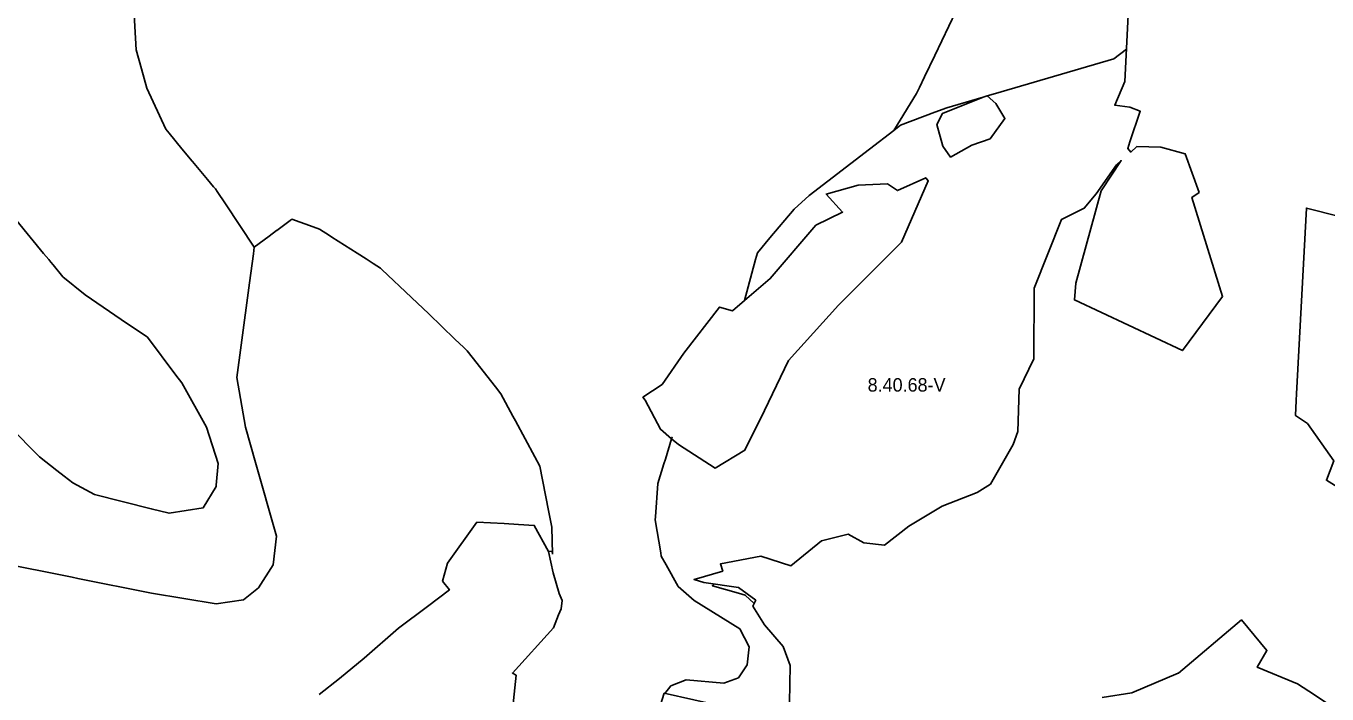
# Model space of a CAD drawing. Extents: x -547623 to -533936, y -1096714 to -1086523.
# Drawn here: x -544707 to -543738, y -1093623 to -1093125 of the extents above; entities that cross this region are included whole.
import ezdxf

# ---------------------------------------------------------------- set-up
doc = ezdxf.new("R2010")
doc.units = 0
doc.layers.add('Vrstva 27', color=7, linetype='Continuous')
doc.layers.add('Vrstva 28', color=7, linetype='Continuous')

msp = doc.modelspace()

# ---------------------------------------------------------------- linework, layer by layer
at = {"layer": 'Vrstva 28'}
for p, q in [((-543998, -1093079), (-544030.47, -1093147.12)), ((-544030.47, -1093147.12), (-543998, -1093079)), ((-544627.2, -1093102.22), (-544625.47, -1093134.21)), ((-544625.47, -1093134.21), (-544627.2, -1093102.22)), ((-544625.47, -1093134.21), (-544625, -1093143)), ((-544625, -1093143), (-544625.47, -1093134.21)), ((-544625, -1093143), (-544621.06, -1093157.03)), ((-544621.06, -1093157.03), (-544625, -1093143)), ((-543897, -1093149.5), (-543887.73, -1093142.39)), ((-543887.73, -1093142.39), (-543897, -1093149.5)), ((-544030.47, -1093147.12), (-544038.02, -1093162.95)), ((-544038.02, -1093162.95), (-544030.47, -1093147.12)), ((-543980.98, -1093174.2), (-543897, -1093149.5)), ((-543897, -1093149.5), (-543980.98, -1093174.2)), ((-544621.06, -1093157.03), (-544617, -1093171.5)), ((-544617, -1093171.5), (-544621.06, -1093157.03)), ((-544038.02, -1093162.95), (-544041.78, -1093170.85)), ((-544041.78, -1093170.85), (-544038.02, -1093162.95)), ((-544617, -1093171.5), (-544603, -1093202)), ((-544603, -1093202), (-544617, -1093171.5)), ((-544041.78, -1093170.85), (-544044, -1093175.5)), ((-544044, -1093175.5), (-544041.78, -1093170.85)), ((-543990.5, -1093177), (-543980.98, -1093174.2)), ((-543980.98, -1093174.2), (-543990.5, -1093177)), ((-544044, -1093175.5), (-544061, -1093203)), ((-544061, -1093203), (-544044, -1093175.5)), ((-544021.5, -1093186), (-543994.35, -1093178.12)), ((-543994.35, -1093178.12), (-544021.5, -1093186)), ((-543991.47, -1093177.28), (-543994.35, -1093178.12)), ((-543994.35, -1093178.12), (-543991.47, -1093177.28)), ((-543990.5, -1093177), (-543991.47, -1093177.28)), ((-543991.47, -1093177.28), (-543990.5, -1093177)), ((-544056, -1093199), (-544030.47, -1093189.38)), ((-544030.47, -1093189.38), (-544056, -1093199)), ((-544030.47, -1093189.38), (-544021.5, -1093186)), ((-544021.5, -1093186), (-544030.47, -1093189.38)), ((-544603, -1093202), (-544600.45, -1093205.07)), ((-544600.45, -1093205.07), (-544603, -1093202)), ((-544061, -1093203), (-544079.02, -1093216.88)), ((-544079.02, -1093216.88), (-544061, -1093203)), ((-544061, -1093203), (-544056, -1093199)), ((-544056, -1093199), (-544061, -1093203)), ((-544600.45, -1093205.07), (-544590.92, -1093216.53)), ((-544590.92, -1093216.53), (-544600.45, -1093205.07)), ((-544590.92, -1093216.53), (-544583.17, -1093225.85)), ((-544583.17, -1093225.85), (-544590.92, -1093216.53)), ((-544079.02, -1093216.88), (-544124, -1093251.5)), ((-544124, -1093251.5), (-544079.02, -1093216.88)), ((-544583.17, -1093225.85), (-544583.06, -1093225.98)), ((-544583.06, -1093225.98), (-544583.17, -1093225.85)), ((-544583.06, -1093225.98), (-544571.91, -1093239.39)), ((-544571.91, -1093239.39), (-544583.06, -1093225.98)), ((-544571.91, -1093239.39), (-544567.33, -1093244.9)), ((-544567.33, -1093244.9), (-544571.91, -1093239.39)), ((-544567.33, -1093244.9), (-544566, -1093246.5)), ((-544566, -1093246.5), (-544567.33, -1093244.9)), ((-544566, -1093246.5), (-544564.7, -1093248.45)), ((-544564.7, -1093248.45), (-544566, -1093246.5)), ((-544564.7, -1093248.45), (-544558.56, -1093257.66)), ((-544558.56, -1093257.66), (-544564.7, -1093248.45)), ((-544124, -1093251.5), (-544135, -1093261.5)), ((-544135, -1093261.5), (-544124, -1093251.5)), ((-544723.86, -1093258.07), (-544693.91, -1093294.48)), ((-544693.91, -1093294.48), (-544723.86, -1093258.07)), ((-544558.56, -1093257.66), (-544537, -1093290)), ((-544537, -1093290), (-544558.56, -1093257.66)), ((-544510.28, -1093269.96), (-544519.25, -1093276.69)), ((-544519.25, -1093276.69), (-544510.28, -1093269.96)), ((-544509, -1093269), (-544510.28, -1093269.96)), ((-544510.28, -1093269.96), (-544509, -1093269)), ((-544493.29, -1093274.75), (-544509, -1093269)), ((-544509, -1093269), (-544493.29, -1093274.75)), ((-544135, -1093261.5), (-544153.16, -1093282.97)), ((-544153.16, -1093282.97), (-544135, -1093261.5)), ((-544520.38, -1093277.54), (-544526.02, -1093281.76)), ((-544526.02, -1093281.76), (-544520.38, -1093277.54)), ((-544520.33, -1093277.5), (-544520.38, -1093277.54)), ((-544520.38, -1093277.54), (-544520.33, -1093277.5)), ((-544519.25, -1093276.69), (-544520.33, -1093277.5)), ((-544520.33, -1093277.5), (-544519.25, -1093276.69)), ((-544488.5, -1093276.5), (-544493.29, -1093274.75)), ((-544493.29, -1093274.75), (-544488.5, -1093276.5)), ((-544481.1, -1093281.22), (-544488.5, -1093276.5)), ((-544488.5, -1093276.5), (-544481.1, -1093281.22)), ((-544537, -1093290), (-544537.64, -1093294.82)), ((-544537.64, -1093294.82), (-544537, -1093290)), ((-544526.02, -1093281.76), (-544537, -1093290)), ((-544537, -1093290), (-544526.02, -1093281.76)), ((-544479.25, -1093282.39), (-544481.1, -1093281.22)), ((-544481.1, -1093281.22), (-544479.25, -1093282.39)), ((-544460.56, -1093294.31), (-544479.25, -1093282.39)), ((-544479.25, -1093282.39), (-544460.56, -1093294.31)), ((-544153.16, -1093282.97), (-544162.5, -1093294)), ((-544162.5, -1093294), (-544153.16, -1093282.97)), ((-544693.91, -1093294.48), (-544690.07, -1093299.15)), ((-544690.07, -1093299.15), (-544693.91, -1093294.48)), ((-544690.07, -1093299.15), (-544688.5, -1093301.05)), ((-544688.5, -1093301.05), (-544690.07, -1093299.15)), ((-544537.64, -1093294.82), (-544540.54, -1093316.42)), ((-544540.54, -1093316.42), (-544537.64, -1093294.82)), ((-544453.75, -1093298.64), (-544460.56, -1093294.31)), ((-544460.56, -1093294.31), (-544453.75, -1093298.64)), ((-544448.53, -1093301.98), (-544453.75, -1093298.64)), ((-544453.75, -1093298.64), (-544448.53, -1093301.98)), ((-544164, -1093299), (-544171.96, -1093329.49)), ((-544171.96, -1093329.49), (-544164, -1093299)), ((-544162.5, -1093294), (-544164, -1093299)), ((-544164, -1093299), (-544162.5, -1093294)), ((-544688.5, -1093301.05), (-544686.8, -1093303.12)), ((-544686.8, -1093303.12), (-544688.5, -1093301.05)), ((-544686.8, -1093303.12), (-544679.5, -1093312)), ((-544679.5, -1093312), (-544686.8, -1093303.12)), ((-544443, -1093305.5), (-544448.53, -1093301.98)), ((-544448.53, -1093301.98), (-544443, -1093305.5)), ((-544441.99, -1093306.46), (-544443, -1093305.5)), ((-544443, -1093305.5), (-544441.99, -1093306.46)), ((-544419.96, -1093327.47), (-544441.99, -1093306.46)), ((-544441.99, -1093306.46), (-544419.96, -1093327.47)), ((-544679.5, -1093312), (-544663, -1093325.5)), ((-544663, -1093325.5), (-544679.5, -1093312)), ((-544540.54, -1093316.42), (-544546.75, -1093362.74)), ((-544546.75, -1093362.74), (-544540.54, -1093316.42)), ((-544663, -1093325.5), (-544636.09, -1093343.73)), ((-544636.09, -1093343.73), (-544663, -1093325.5)), ((-544407.19, -1093339.65), (-544419.96, -1093327.47)), ((-544419.96, -1093327.47), (-544407.19, -1093339.65)), ((-544636.09, -1093343.73), (-544616.5, -1093357)), ((-544616.5, -1093357), (-544636.09, -1093343.73)), ((-544387.61, -1093358.32), (-544407.19, -1093339.65)), ((-544407.19, -1093339.65), (-544387.61, -1093358.32)), ((-544616.5, -1093357), (-544595.41, -1093385.11)), ((-544595.41, -1093385.11), (-544616.5, -1093357)), ((-544546.75, -1093362.74), (-544550, -1093387)), ((-544550, -1093387), (-544546.75, -1093362.74)), ((-544381.12, -1093364.5), (-544387.61, -1093358.32)), ((-544387.61, -1093358.32), (-544381.12, -1093364.5)), ((-544378.5, -1093367), (-544381.12, -1093364.5)), ((-544381.12, -1093364.5), (-544378.5, -1093367)), ((-544374.84, -1093371.69), (-544378.5, -1093367)), ((-544378.5, -1093367), (-544374.84, -1093371.69)), ((-544357.42, -1093393.98), (-544374.84, -1093371.69)), ((-544374.84, -1093371.69), (-544357.42, -1093393.98)), ((-544595.41, -1093385.11), (-544591, -1093391)), ((-544591, -1093391), (-544595.41, -1093385.11)), ((-544550, -1093387), (-544543.5, -1093424)), ((-544543.5, -1093424), (-544550, -1093387)), ((-544591, -1093391), (-544572.5, -1093424)), ((-544572.5, -1093424), (-544591, -1093391)), ((-544353.5, -1093399), (-544357.42, -1093393.98)), ((-544357.42, -1093393.98), (-544353.5, -1093399)), ((-544344.57, -1093415.62), (-544353.5, -1093399)), ((-544353.5, -1093399), (-544344.57, -1093415.62)), ((-544342.59, -1093419.32), (-544344.57, -1093415.62)), ((-544344.57, -1093415.62), (-544342.59, -1093419.32)), ((-544697, -1093446), (-544719.39, -1093423.35)), ((-544719.39, -1093423.35), (-544697, -1093446)), ((-544572.5, -1093424), (-544564, -1093451)), ((-544564, -1093451), (-544572.5, -1093424)), ((-544543.5, -1093424), (-544536.06, -1093450.21)), ((-544536.06, -1093450.21), (-544543.5, -1093424)), ((-544328.21, -1093446.09), (-544342.59, -1093419.32)), ((-544342.59, -1093419.32), (-544328.21, -1093446.09)), ((-544226.31, -1093432.52), (-544230.95, -1093447.78)), ((-544230.95, -1093447.78), (-544226.31, -1093432.52)), ((-544226, -1093431.5), (-544226.31, -1093432.52)), ((-544226.31, -1093432.52), (-544226, -1093431.5)), ((-543968.51, -1093427.13), (-543971.95, -1093436.83)), ((-544683.95, -1093456.18), (-544697, -1093446)), ((-544697, -1093446), (-544683.95, -1093456.18)), ((-544564, -1093451), (-544565.43, -1093467.15)), ((-544565.43, -1093467.15), (-544564, -1093451)), ((-544536.06, -1093450.21), (-544520.5, -1093505)), ((-544520.5, -1093505), (-544536.06, -1093450.21)), ((-544324.5, -1093453), (-544328.21, -1093446.09)), ((-544328.21, -1093446.09), (-544324.5, -1093453)), ((-544317.99, -1093485.92), (-544324.5, -1093453)), ((-544324.5, -1093453), (-544317.99, -1093485.92)), ((-544232.02, -1093451.29), (-544236.5, -1093466)), ((-544236.5, -1093466), (-544232.02, -1093451.29)), ((-544230.95, -1093447.78), (-544232.02, -1093451.29)), ((-544232.02, -1093451.29), (-544230.95, -1093447.78)), ((-544678.52, -1093460.41), (-544683.95, -1093456.18)), ((-544683.95, -1093456.18), (-544678.52, -1093460.41)), ((-544672, -1093465.5), (-544678.52, -1093460.41)), ((-544678.52, -1093460.41), (-544672, -1093465.5)), ((-544656, -1093474), (-544672, -1093465.5)), ((-544672, -1093465.5), (-544656, -1093474)), ((-544613.77, -1093484.65), (-544656, -1093474)), ((-544656, -1093474), (-544613.77, -1093484.65)), ((-544565.5, -1093468), (-544575, -1093484)), ((-544575, -1093484), (-544565.5, -1093468)), ((-544565.43, -1093467.15), (-544565.5, -1093468)), ((-544565.5, -1093468), (-544565.43, -1093467.15)), ((-544236.5, -1093466), (-544238.33, -1093490.74)), ((-544238.33, -1093490.74), (-544236.5, -1093466)), ((-544575, -1093484), (-544600.5, -1093488)), ((-544600.5, -1093488), (-544575, -1093484)), ((-544600.5, -1093488), (-544613.77, -1093484.65)), ((-544613.77, -1093484.65), (-544600.5, -1093488)), ((-544316.75, -1093492.2), (-544317.99, -1093485.92)), ((-544317.99, -1093485.92), (-544316.75, -1093492.2)), ((-544315.5, -1093498.5), (-544316.75, -1093492.2)), ((-544316.75, -1093492.2), (-544315.5, -1093498.5)), ((-544238.33, -1093490.74), (-544238.5, -1093493)), ((-544238.5, -1093493), (-544238.33, -1093490.74)), ((-544238.5, -1093493), (-544234.41, -1093517.56)), ((-544234.41, -1093517.56), (-544238.5, -1093493)), ((-544367, -1093494.5), (-544367.2, -1093494.81)), ((-544367.2, -1093494.81), (-544367.2, -1093494.81)), ((-544350.5, -1093495.78), (-544350.54, -1093495.78)), ((-544315.02, -1093518.45), (-544315.5, -1093498.5)), ((-544315.5, -1093498.5), (-544315.02, -1093518.45)), ((-544520.5, -1093505), (-544523, -1093526.5)), ((-544523, -1093526.5), (-544520.5, -1093505)), ((-544315.32, -1093516.39), (-544317.96, -1093516.56)), ((-544315.02, -1093518.45), (-544315.32, -1093516.39)), ((-544234.41, -1093517.56), (-544234, -1093520)), ((-544234, -1093520), (-544234.41, -1093517.56)), ((-544234, -1093520), (-544230.43, -1093526.43)), ((-544230.43, -1093526.43), (-544234, -1093520)), ((-544672.58, -1093535.73), (-544729, -1093524.5)), ((-544729, -1093524.5), (-544672.58, -1093535.73)), ((-544523, -1093526.5), (-544534, -1093543.5)), ((-544534, -1093543.5), (-544523, -1093526.5)), ((-544230.43, -1093526.43), (-544221.5, -1093542.5)), ((-544221.5, -1093542.5), (-544230.43, -1093526.43)), ((-544668.51, -1093536.54), (-544672.58, -1093535.73)), ((-544672.58, -1093535.73), (-544668.51, -1093536.54)), ((-544613.5, -1093547.5), (-544668.51, -1093536.54)), ((-544668.51, -1093536.54), (-544613.5, -1093547.5)), ((-544194.73, -1093540.73), (-544196, -1093542)), ((-544196, -1093542), (-544176.5, -1093547.5)), ((-544565.5, -1093555.5), (-544613.5, -1093547.5)), ((-544613.5, -1093547.5), (-544565.5, -1093555.5)), ((-544534, -1093543.5), (-544545, -1093552.5)), ((-544545, -1093552.5), (-544534, -1093543.5)), ((-544221.5, -1093542.5), (-544209.5, -1093553)), ((-544209.5, -1093553), (-544221.5, -1093542.5)), ((-544176.5, -1093547.5), (-544171.5, -1093549)), ((-544171.5, -1093549), (-544164.75, -1093555.15)), ((-544545, -1093552.5), (-544565.5, -1093555.5)), ((-544565.5, -1093555.5), (-544545, -1093552.5)), ((-544209.5, -1093553), (-544175.5, -1093574)), ((-544175.5, -1093574), (-544209.5, -1093553)), ((-544175.5, -1093574), (-544168.5, -1093587.5)), ((-544168.5, -1093587.5), (-544175.5, -1093574)), ((-544168.5, -1093587.5), (-544170, -1093601)), ((-544170, -1093601), (-544168.5, -1093587.5)), ((-544170, -1093601), (-544176.5, -1093610.5)), ((-544176.5, -1093610.5), (-544170, -1093601)), ((-544227, -1093616.5), (-544231.48, -1093622.21)), ((-544231.48, -1093622.21), (-544227, -1093616.5)), ((-544215.5, -1093612), (-544227, -1093616.5)), ((-544227, -1093616.5), (-544215.5, -1093612)), ((-544187.5, -1093614.5), (-544215.5, -1093612)), ((-544215.5, -1093612), (-544187.5, -1093614.5)), ((-544176.5, -1093610.5), (-544187.5, -1093614.5)), ((-544187.5, -1093614.5), (-544176.5, -1093610.5)), ((-544231.48, -1093622.21), (-544231.48, -1093622.21)), ((-544231.48, -1093622.21), (-544231.48, -1093622.21))]:
    msp.add_line(p, q, dxfattribs=at)
for points in [[(-543885.89, -1093107.07), (-543888.99, -1093166.48), (-543896.36, -1093184.19), (-543885.16, -1093185.62), (-543877.41, -1093188.69), (-543885.07, -1093211.55), (-543886.71, -1093216.35), (-543884.47, -1093219.03), (-543879.9, -1093214.92), (-543862.21, -1093215.39), (-543843.89, -1093220.32), (-543833.59, -1093249.07), (-543839.05, -1093252.98), (-543816.14, -1093326.66), (-543846.07, -1093366.93), (-543926.49, -1093329.19), (-543925.29, -1093316.71), (-543906.48, -1093247.86), (-543891.56, -1093225.41), (-543895.07, -1093228.63), (-543910.35, -1093250.19), (-543919.1, -1093260.83), (-543936.18, -1093269.34), (-543956.53, -1093320.47), (-543956.78, -1093372.98), (-543967.49, -1093395.71), (-543968.51, -1093427.13), (-543971.95, -1093436.83), (-543988.87, -1093466.28), (-543998.81, -1093472.63), (-544024.93, -1093482.74), (-544049.84, -1093497.69), (-544067.95, -1093511.85), (-544083.11, -1093510.13), (-544095, -1093503.7), (-544114.86, -1093508.66), (-544137.64, -1093527.2), (-544159.82, -1093519.92), (-544189.98, -1093525.79), (-544188.23, -1093531.13), (-544209.56, -1093537.26), (-544202.29, -1093539.64), (-544176.61, -1093543.34), (-544163.71, -1093552.88), (-544165.76, -1093557.36), (-544157.24, -1093571.16), (-544143.3, -1093587.3), (-544138.16, -1093601.33), (-544138.53, -1093629.26)], [(-543994.35, -1093178.12), (-544024.54, -1093190.26), (-544028.77, -1093198.63), (-544024.51, -1093214.73), (-544018.61, -1093222.8), (-544002.92, -1093213.81), (-543989.26, -1093209.08), (-543978.2, -1093194.02), (-543984.86, -1093182.98), (-543991.47, -1093177.28), (-543994.34, -1093178.12), (-543994.35, -1093178.12)], [(-544226.31, -1093432.52), (-544221.22, -1093436.9), (-544193.88, -1093454.36), (-544171.8, -1093441.13), (-544157.13, -1093411.58), (-544139.31, -1093374.29), (-544101.99, -1093332.99), (-544055.26, -1093286.27), (-544035.25, -1093240.45), (-544037.15, -1093238.19), (-544058.28, -1093247.77), (-544065.57, -1093242.69), (-544087.44, -1093243.8), (-544111.23, -1093250.31), (-544099.07, -1093263.79), (-544118.88, -1093273.5), (-544152.93, -1093313.23), (-544171.96, -1093329.49), (-544171.96, -1093329.49), (-544171.97, -1093329.49), (-544181.09, -1093337.29), (-544190.73, -1093334.46), (-544217.24, -1093368.77), (-544233.35, -1093392.09), (-544247.74, -1093401.7), (-544245.98, -1093403.87), (-544234.49, -1093425.49), (-544226.31, -1093432.52), (-544226.31, -1093432.52), (-544226, -1093431.5), (-544226.31, -1093432.52), (-544226.31, -1093432.52)], [(-544719.39, -1093423.35), (-544697, -1093446), (-544683.95, -1093456.18), (-544678.52, -1093460.41), (-544672, -1093465.5), (-544656, -1093474), (-544613.77, -1093484.65), (-544600.5, -1093488), (-544575, -1093484), (-544565.5, -1093468), (-544565.43, -1093467.15), (-544564, -1093451), (-544572.5, -1093424), (-544591, -1093391), (-544595.41, -1093385.11), (-544616.5, -1093357), (-544636.09, -1093343.73), (-544663, -1093325.5), (-544679.5, -1093312), (-544686.8, -1093303.12), (-544688.5, -1093301.05), (-544690.07, -1093299.15), (-544693.91, -1093294.48), (-544723.86, -1093258.07)], [(-543685.56, -1093496.59), (-543738.79, -1093463.49), (-543733.22, -1093448.93), (-543752.96, -1093421.2), (-543761.76, -1093415.26), (-543761.32, -1093404.04), (-543761.06, -1093399.15), (-543753.78, -1093260.76), (-543681.01, -1093279.31)], [(-544345.05, -1093636.88), (-544342.12, -1093608.69), (-544344.88, -1093607.09), (-544314.3, -1093573.38), (-544310.45, -1093563.66), (-544308.47, -1093559.19), (-544307.92, -1093553.06), (-544309.95, -1093547.78), (-544314.57, -1093532.3), (-544317.96, -1093516.56), (-544328.58, -1093497.05), (-544340.44, -1093496.36), (-544351.12, -1093495.75), (-544371.24, -1093494.58), (-544393.17, -1093525.2), (-544396.82, -1093538.69), (-544391.76, -1093545.01), (-544408, -1093557.48), (-544429.72, -1093573.72), (-544455.34, -1093596.09), (-544473.61, -1093611.03), (-544488.81, -1093622.94)], [(-544164.75, -1093555.15), (-544171.5, -1093549), (-544176.5, -1093547.5), (-544196, -1093542), (-544194.73, -1093540.73)], [(-543905.85, -1093625.2), (-543883.8, -1093621.66), (-543849.13, -1093607.17), (-543849, -1093607.11), (-543802.11, -1093567.52), (-543783.08, -1093590.28), (-543790.32, -1093602.67), (-543760.35, -1093614.98), (-543752.03, -1093620.49), (-543701.51, -1093653.95)], [(-544187.58, -1093631.95), (-544231.86, -1093622.13), (-544253.47, -1093690.89)]]:
    msp.add_lwpolyline(points, dxfattribs=at)

# ---------------------------------------------------------------- texts
at = {"layer": 'Vrstva 27'}
msp.add_text('8.40.68-V', height=10, dxfattribs=at).set_placement((-544080.39, -1093397.44))

doc.saveas('drawing.dxf')
